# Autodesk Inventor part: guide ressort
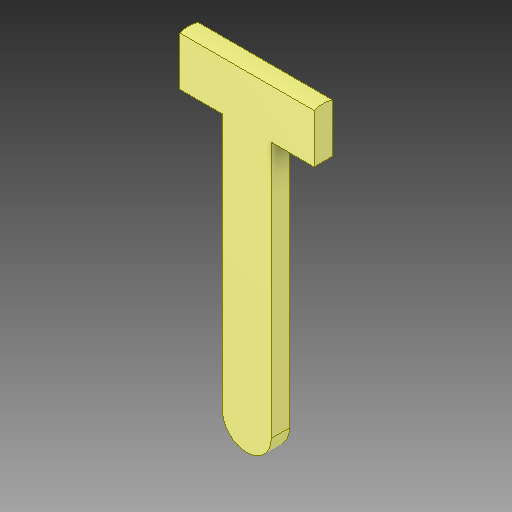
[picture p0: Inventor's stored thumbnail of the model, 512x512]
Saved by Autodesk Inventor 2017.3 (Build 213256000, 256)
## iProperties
Created: 2007-11
Part Number: guide ressort
Material: Générique
Document SubType Name: Modeling
Designer: ficho
Density: 1 g/cm^3
Appearance: Par défaut
Author: ficho
Sending System: SolidWorks 2009
Last Author: christophe
Last Saved: 2011-02-10
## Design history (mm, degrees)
extrude "Extrusion3"
node "Solide1"
